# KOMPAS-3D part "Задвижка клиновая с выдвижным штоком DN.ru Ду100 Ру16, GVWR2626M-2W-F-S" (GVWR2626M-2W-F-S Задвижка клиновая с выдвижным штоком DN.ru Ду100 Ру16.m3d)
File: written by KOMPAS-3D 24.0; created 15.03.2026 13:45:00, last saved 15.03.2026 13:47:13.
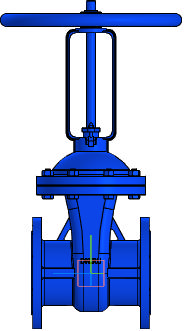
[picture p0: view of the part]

Document properties: Автор: R2D2; Полное имя файла: E:\Работа\Зайцев\GVWR2626M-2W-F-S Задвижка клиновая с выдвижным штоком DN.ru Ду50-300 Ру16\DN100\GVWR2626M-2W-F-S Задвижка клиновая с выдвижным штоком DN.ru Ду100 Ру16.m3d

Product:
- Part/product: Задвижка клиновая с выдвижным штоком DN.ru Ду100 Ру16  | designation GVWR2626M-2W-F-S
    Масса: 35
    Раздел спецификации: Прочие изделия
    Примечание: D040-10502

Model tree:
1. Операция без истории:1

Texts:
  GVWR2626M-2W-F-S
